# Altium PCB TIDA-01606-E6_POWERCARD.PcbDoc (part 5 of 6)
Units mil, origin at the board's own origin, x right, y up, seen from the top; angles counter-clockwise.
Board outline 13779.53 x 7874.02 mil, 4 copper layers (Top Layer, Gnd Layer, Pwr Layer, Bottom Layer), stack 94.4 mil thick; 550 components, 292 nets, 1594 pads, 572 vias.
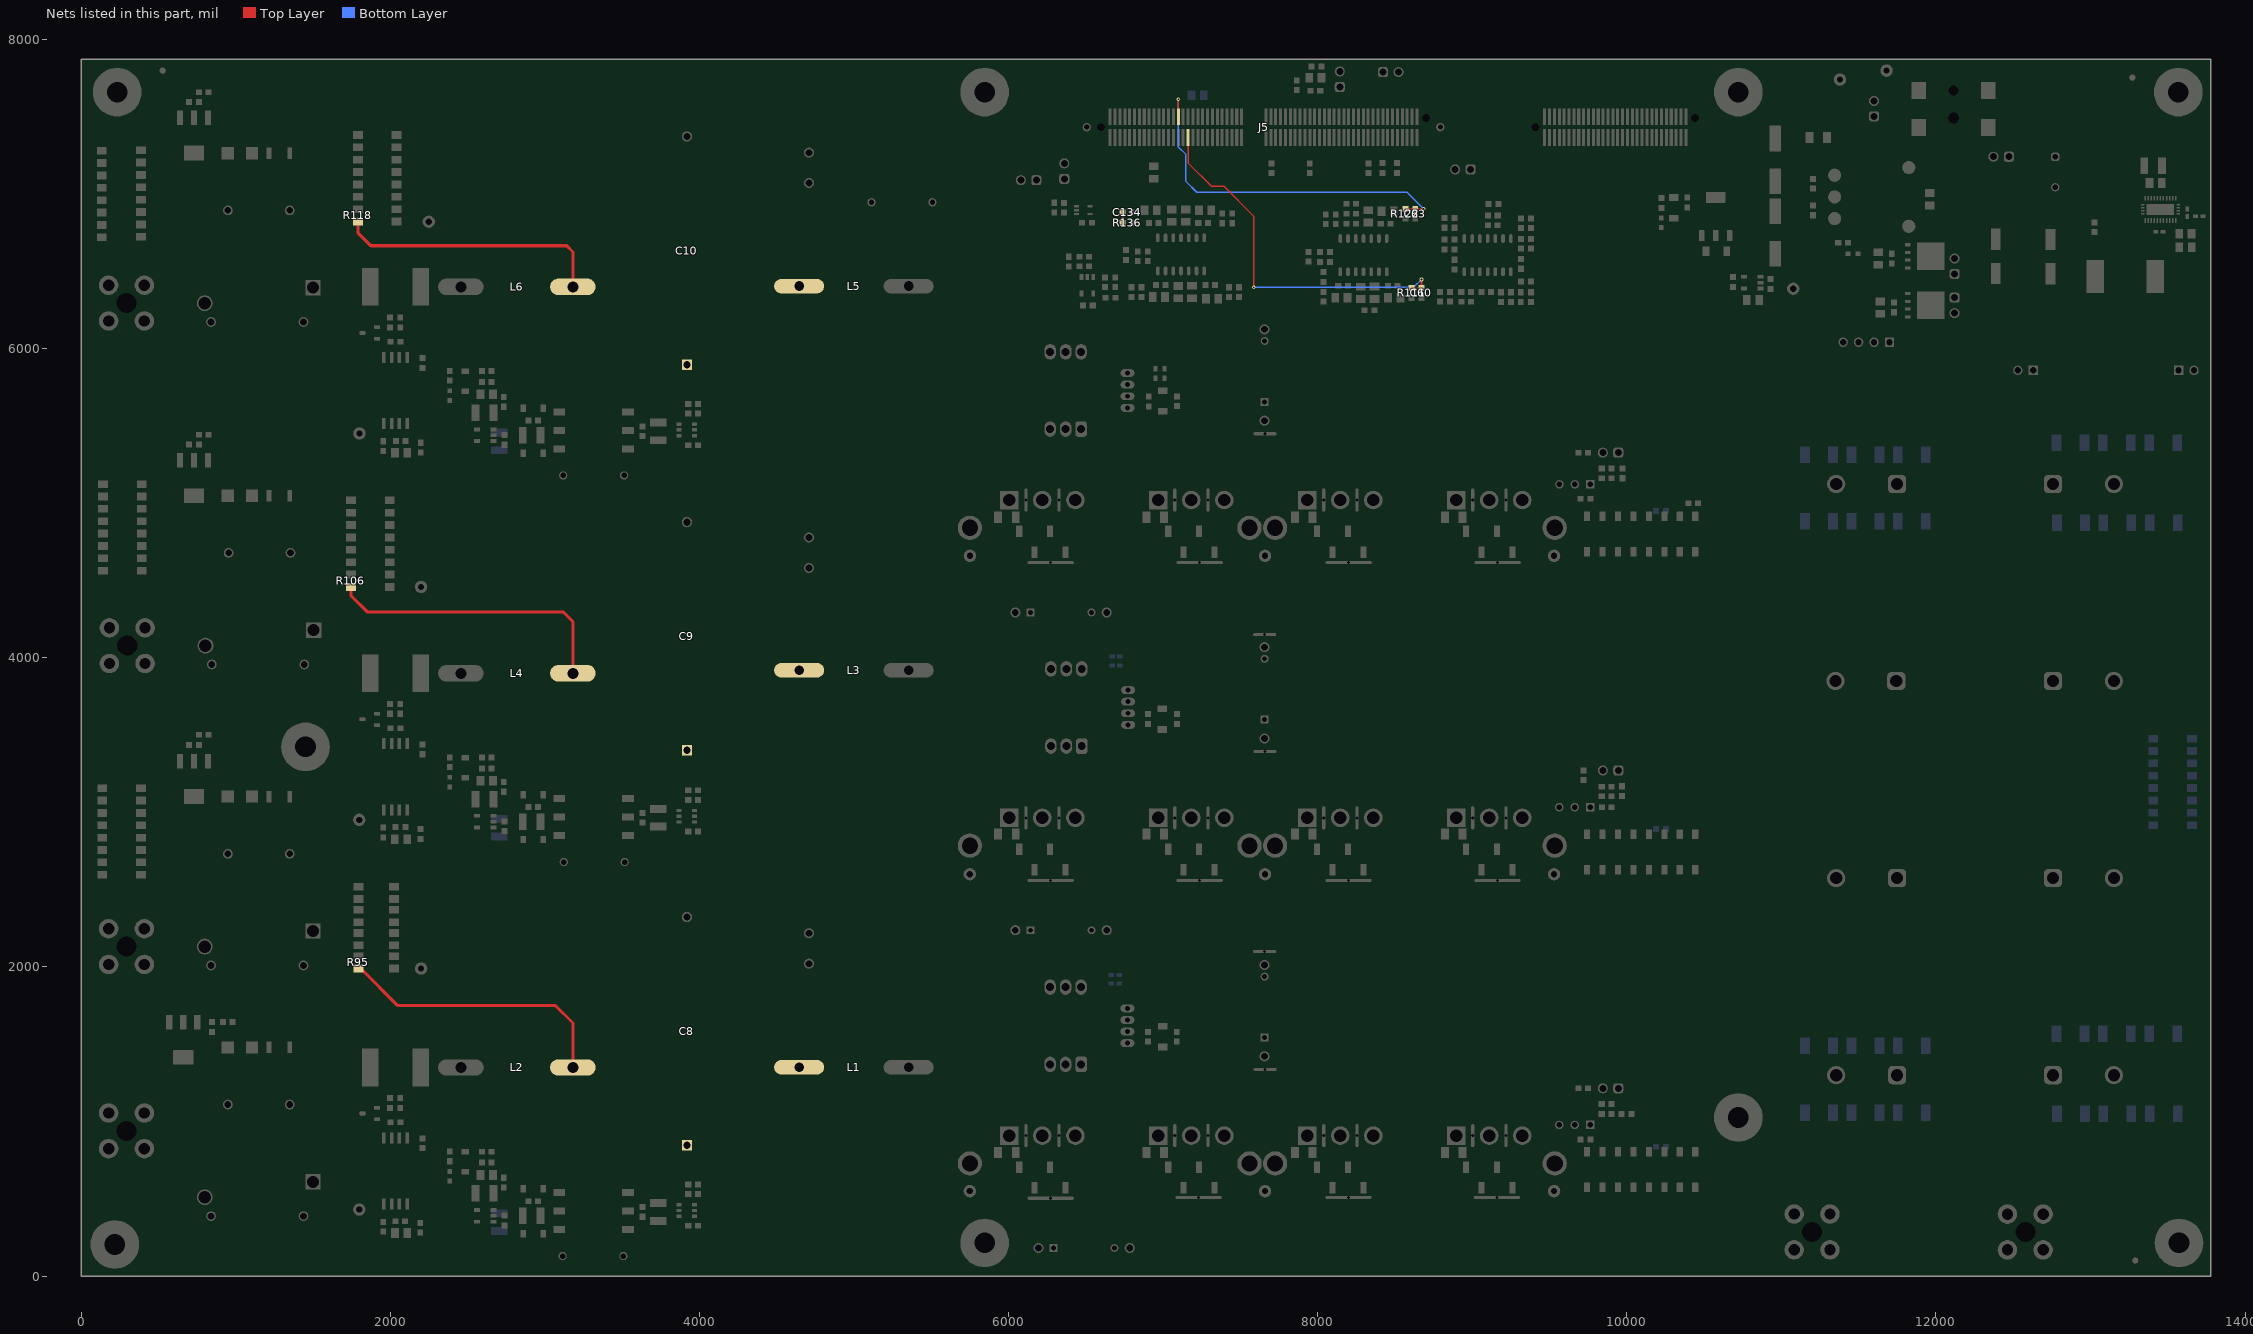
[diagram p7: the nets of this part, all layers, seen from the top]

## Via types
v1: diameter 32, hole 16, Top Layer to Bottom Layer, 336 vias
v2: diameter 24, hole 12, Top Layer to Bottom Layer, 140 vias
v3: diameter 50, hole 28, Top Layer to Bottom Layer, tented both sides, 65 vias
v4: diameter 52, hole 28, Top Layer to Bottom Layer, 14 vias
v5: diameter 19.68, hole 7.87, Top Layer to Bottom Layer, 10 vias
v6: diameter 50, hole 28, Top Layer to Bottom Layer, 7 vias

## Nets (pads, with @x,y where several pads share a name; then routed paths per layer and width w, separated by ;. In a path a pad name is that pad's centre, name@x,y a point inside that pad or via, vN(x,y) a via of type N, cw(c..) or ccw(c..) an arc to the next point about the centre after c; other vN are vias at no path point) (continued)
VINV_SEN_B: C60.2 J5.33 R111.2 | length 2417.9
  Top Layer w10: J5.33@7161.93,7366.21 7161.92,7202.07 7312,7052 7392,7052 7586,6858 7586,6398 v2(7587,6397) ; R111.2@8607.7,6392.5 C60.2@8671.7,6392.5 8672,6392.8 v2(8672,6448)
  Bottom Layer w10: v2(7587,6397) 8621,6397 v2(8672,6448)
VINV_SEN_C: C63.2 J5.30 R122.2 | length 2400.2
  Top Layer w10: J5.30@7098.93,7500.07 7098.93,7615.56 7099,7615.5 v2(7099,7614) ; R122.2@8567.7,6904.5 C63.2@8631.7,6904.5 8631,6905.2 v2(8685.8,6905.2)
  Bottom Layer w10: v2(7099,7614) 7099,7305 7148,7256 7148,7082 7218,7012 8579,7012 v2(8685.8,6905.2)
VMID_SEN_C: C134.2 R136.2 | length 69.9
  Top Layer w10: R136.2@6738.5,6813.43 C134.2@6738.5,6883.38
Vsen_A: C8.1 L1.1 L2.1 R95.1 | length 1820.9
  Top Layer w20: R95.1@1795,1990 1809.64,1990 2049.64,1750 3070,1750 3182.2,1637.8 L2.1@3182.2,1350
Vsen_B: C9.1 L3.1 L4.1 R106.1 | length 1895.9
  Top Layer w20: R106.1@1746.45,4459 1746.45,4401.59 1850.63,4297.4 3117.6,4297.4 3182.2,4232.8 L4.1@3182.2,3900
Vsen_C: C10.1 L5.1 L6.1 R118.1 | length 1741.6
  Top Layer w20: R118.1@1791.06,6823 1791.06,6750.03 1875.2,6665.89 3142.5,6665.89 3182.2,6626.19 L6.1@3182.2,6400
pads on no net: FID1.1 FID2.1 FID3.1 FID4.1 FID5.1 FID6.1 H1.0 H2.0 H3.0 H4.0 H5.0 H6.0 H7.0 H8.0 H9.0 H10.0 H11.0 H12.0 H13.0 H14.0 H15.0 H16.0 H17.0 H18.0 H19.1 H19.2 H20.1 H20.2 H21.1 H21.2 H22.1 H22.2 H23.1 H23.2 H24.1 H24.2 J1. J2. J3. J4. J5.1 J5.2 J5.3 J5.4 J5.5 J5.6 J5.8 J5.23 J5.24 J5.26 J5.27 J5.36 J5.39 J5.40 J5.41 J5.43 J5.44 J5.45 J5.66 J5.67 J5.68 J5.69 J5.70 J5.71 J5.72 J5.73 J5.74 J5.77 J5.78 J5.80 J5.82 J5.91 J5.93 J5.94 J5.96 J5.100 J5.102 J5.104 J5.106 J5.113 J5.114 J5.115 J5.116 J5.117 J5.118 J5.119 J5.120 J5.181 J5.182 J5.185 J5.186 J7.3 J7.4 J9.3 J12.3 J13.61 J13.62 J13.121 J13.122 J13.123 J13.124 J13.125 J13.126 J13.127 J13.128 J13.129 J13.130 J13.131 J13.132 J13.133 J13.134 J13.135 J13.136 J13.137 J13.138 J13.139 J13.140 J13.141 J13.142 J13.143 J13.144 J13.145 J13.146 J13.147 J13.148 J13.149 J13.150 J13.151 J13.152 J13.153 J13.154 J13.155 J13.156 J13.157 J13.159 J13.160 J13.161 J13.162 J13.163 J13.164 J13.165 J13.166 J13.167 J13.168 J13.169 J13.170 J13.171 J13.172 J13.173 J13.174 J13.175 J13.176 J13.177 J13.178 J14.3 J14.4 J15.3 J16.3 J17.3 J18.3 J18.4 J19.3 J19.4 J20.3 J21.3 J21.4 J22.3 J22.4 J23.9 J24.9 J25.9 J31. J32. J33.MH1 J33.MH2 LBL1.0 Q13.9@11912.28,6223.91 Q13.9@11912.28,6281 Q13.9@11912.28,6338.09 Q13.9@11948.9,6281 Q13.9@11982.36,6223.91 Q13.9@11982.36,6281 Q13.9@11982.36,6338.09 Q14.9@11913.04,6540.66 Q14.9@11913.04,6597.75 Q14.9@11913.04,6654.83 Q14.9@11949.65,6597.75 Q14.9@11983.12,6540.66 Q14.9@11983.12,6597.75 Q14.9@11983.12,6654.83 R177.1 U10.4 U10.5 U11.10 U11.11 U11.31@13385.31,6881.46 U11.31@13385.31,6920.83 U11.31@13430.19,6881.46 U11.31@13430.19,6920.83 U11.31@13475.07,6881.46 U11.31@13475.07,6920.83 U11.31@13519.95,6881.46 U11.31@13519.95,6920.83 U12.5 U21.4 U21.5 U23.4 U23.5

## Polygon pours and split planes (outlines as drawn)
DC- on Top Layer "GN" (solid, remove dead copper, pour order 826): 55 vertices, not listed, extent 6387,37 11414,5204
Vsen_B on Top Layer "GN" (solid, remove dead copper, pour order 820): 3010,3380 3010,4000 3030,4020 4790,4020 4830,3980 4830,3600 4790,3560 4180,3560 3980,3360 3050,3360 3030,3360
Q4A on Top Layer "TOP_LAYER_Q4A_P818" (solid, remove dead copper, pour order 818): 8981.34,667.87 8981.34,937.87 8961.34,957.87 8861.34,957.87 8861.34,687.87 8881.34,667.87
Q3A on Top Layer "TOP_LAYER_Q3A_P816" (solid, remove dead copper, pour order 816): 8017.56,667.87 8017.56,937.87 7997.56,957.87 7897.56,957.87 7897.56,687.87 7917.56,667.87
Q1A on Top Layer "TOP_LAYER_Q1A_P814" (solid, remove dead copper, pour order 814): 7053.78,667.87 7053.78,937.87 7033.78,957.87 6933.78,957.87 6933.78,687.87 6953.78,667.87
Q2A on Top Layer "TOP_LAYER_Q2A_P812" (solid, remove dead copper, pour order 812): 6090,667.87 6090,937.87 6070,957.87 5970,957.87 5970,687.87 5990,667.87
Q4B on Top Layer "TOP_LAYER_Q4B_P810" (solid, remove dead copper, pour order 810): 8981.34,2723.94 8981.34,2993.94 8961.34,3013.94 8861.34,3013.94 8861.34,2743.94 8881.34,2723.94
Q3B on Top Layer "TOP_LAYER_Q3B_P808" (solid, remove dead copper, pour order 808): 8017.56,2723.94 8017.56,2993.94 7997.56,3013.94 7897.56,3013.94 7897.56,2743.94 7917.56,2723.94
Q1B on Top Layer "TOP_LAYER_Q1B_P806" (solid, remove dead copper, pour order 806): 7053.78,2723.94 7053.78,2993.94 7033.78,3013.94 6933.78,3013.94 6933.78,2743.94 6953.78,2723.94
Q2B on Top Layer "TOP_LAYER_Q2B_P804" (solid, remove dead copper, pour order 804): 6090,2723.94 6090,2993.94 6070,3013.94 5970,3013.94 5970,2743.94 5990,2723.94
Q4C on Top Layer "TOP_LAYER_Q4C_P802" (solid, remove dead copper, pour order 802): 8981.34,4780 8981.34,5050 8961.34,5070 8861.34,5070 8861.34,4800 8881.34,4780
Q3C on Top Layer "TOP_LAYER_Q3C_P800" (solid, remove dead copper, pour order 800): 8017.56,4780 8017.56,5050 7997.56,5070 7897.56,5070 7897.56,4800 7917.56,4780
Q1C on Top Layer "TOP_LAYER_Q1C_P798" (solid, remove dead copper, pour order 798): 7053.78,4780 7053.78,5050 7033.78,5070 6933.78,5070 6933.78,4800 6953.78,4780
Vsen_A on Top Layer "GN" (solid, remove dead copper, pour order 766): 3010,830 3010,1450 3030,1470 4780,1470 4830,1420 4830,1060 4780,1010 4180,1010 3980,810 3030,810
NetC8_2 on Top Layer "TOP_LAYER_NETC8_2_P758" (solid, remove dead copper, pour order 758): 3860,2370 3860,2310 3890,2280 4570,2280 4690,2160 4740,2160 4770,2190 4770,2280 4770,2370 4740,2400 3890,2400
NetC9_2 on Top Layer "TOP_LAYER_NETC9_2_P756" (solid, remove dead copper, pour order 756): 3860,4930 3860,4860 3885,4835 4570,4835 4690,4715 4745,4715 4770,4740 4770,4835 4770,4930 4745,4955 3885,4955
Vinv_B on Top Layer "M1 Board Outline-No Net" (solid, remove dead copper, pour order 690): 1915,3760 1590,3760 1410,3940 1410,4220 1428,4238 1614,4238 1802,4050 1915,4050 1925,4040 1925,3770
3.3V on Top Layer "GN" (solid, remove dead copper, pour order 686): 2267,5364 2174,5364 2161,5377 2161,5459 2178,5476 2257,5476 2269,5464 2269,5366 2267,5364
3.3V on Top Layer "GN" (solid, remove dead copper, pour order 684): 2267,314 2174,314 2161,327 2161,409 2178,426 2257,426 2269,414 2269,316 2267,314
3.3V on Top Layer "GN" (solid, remove dead copper, pour order 678): 2267,2864 2174,2864 2161,2877 2161,2959 2178,2976 2257,2976 2269,2964 2269,2866 2267,2864
QC_N on Top Layer "GN" (solid, remove dead copper, pour order 508): 25 vertices, not listed, extent 8316,4963 9421,5382
IIND_C on Top Layer "GN" (solid, remove dead copper, pour order 502): 39 vertices, not listed, extent 6169,4969 8194,5530
IGRID_A on Top Layer "TOP_LAYER_IGRID_A_P054" (solid, remove dead copper, pour order 54): 2611,1465 2611,1247 2574,1210 2153.9,1210 2143.9,1220 2143.9,1490 2153.9,1500 2576,1500
IGRID_B on Top Layer "TOP_LAYER_IGRID_B_P048" (solid, remove dead copper, pour order 48): 2610,4020 2610,3789 2581,3760 2153.9,3760 2143.9,3770 2143.9,4040 2153.9,4050 2580,4050
IGRID_C on Top Layer "TOP_LAYER_IGRID_C_P038" (solid, remove dead copper, pour order 38): 2610,6527 2610,6282 2588,6260 2153.9,6260 2143.9,6270 2143.9,6540 2153.9,6550 2587,6550
Vinv_C on Top Layer "TOP_LAYER_VINV_C_P036" (solid, remove dead copper, pour order 36): 1620,6260 1489.56,6129.56 1427.69,6129.56 1408.19,6149.06 1408.19,6534.78 1423.41,6550 1465,6550 1915,6550 1925,6540 1925,6270 1915,6260
NEU on Top Layer "TOP_LAYER_NEU_P010" (solid, remove dead copper, pour order 10): 90,1108 142,1160 420,1160 550,1030 880,700 880,362.72 847.28,330 515,330 90,755
PH_C on Top Layer "TOP_LAYER_PH_C_P006" (solid, remove dead copper, pour order 6): 809,6552 879,6482 879,6109 825,6055 95,6055 70,6080 70,6513 109,6552
NetC10_2 on Top Layer "TOP_LAYER_NETC10_2_P084" (solid, remove dead copper, pour order 84): 3860,7430 3860,7350 3880,7330 4570,7330 4690,7210 4740,7210 4770,7240 4770,7330 4770,7420 4740,7450 3880,7450
PH_B on Top Layer "TOP_LAYER_PH_B_P086" (solid, remove dead copper, pour order 86): 814,4336 880,4270 880,3889 830,3839 100,3839 75,3864 75,4297 114,4336
PH_A on Top Layer "TOP_LAYER_PH_A_P088" (solid, remove dead copper, pour order 88): 809,2389 879,2319 879,1946 825,1892 95,1892 70,1917 70,2350 109,2389
Vinv_A on Top Layer "M1 Board Outline-No Net" (solid, remove dead copper, pour order 116): 1410,2268.66 1410,1934 1729,1615 1729,1248 1752,1225 1843,1225 1923,1225 1928,1230 1928,1750 1658,2020 1658,2278 1644,2292 1433.34,2292
NetC31_1 on Top Layer "M1 Board Outline-No Net" (solid, remove dead copper, pour order 212): 7122,5651 7131,5642 7131,5581 7121,5571 6756,5571 6746,5581 6741,5586 6741,5631 6741,5639 6753,5651
5V on Top Layer "M1 Board Outline-No Net" (solid, remove dead copper, pour order 214): 7056,5683 7056,5764 7064,5772 7170,5772 7178,5764 7178,5678 7166,5666 7066,5666 7056,5676
GND on Top Layer "M1 Board Outline-No Net" (solid, remove dead copper, pour order 216): 6962,5775 6908,5775 6896,5763 6842,5709 6807,5709 6751,5709 6744,5702 6744,5681 6748,5677 7009,5677 7033,5701 7033,5765 7023,5775
GND on Top Layer "M1 Board Outline-No Net" (solid, remove dead copper, pour order 218): 6962,3718.94 6908,3718.94 6896,3706.94 6842,3652.94 6807,3652.94 6751,3652.94 6744,3645.94 6744,3624.94 6748,3620.94 7009,3620.94 7033,3644.94 7033,3708.94 7023,3718.94
5V on Top Layer "M1 Board Outline-No Net" (solid, remove dead copper, pour order 220): 7056,3626.94 7056,3707.94 7064,3715.94 7170,3715.94 7178,3707.94 7178,3621.94 7166,3609.94 7066,3609.94 7056,3619.94
NetC24_1 on Top Layer "M1 Board Outline-No Net" (solid, remove dead copper, pour order 222): 7122,3594.94 7131,3585.94 7131,3524.94 7121,3514.94 6756,3514.94 6746,3524.94 6741,3529.94 6741,3574.94 6741,3582.94 6753,3594.94
GND on Top Layer "M1 Board Outline-No Net" (solid, remove dead copper, pour order 224): 6962,1662.87 6908,1662.87 6896,1650.87 6842,1596.87 6807,1596.87 6751,1596.87 6744,1589.87 6744,1568.87 6748,1564.87 7009,1564.87 7033,1588.87 7033,1652.87 7023,1662.87
5V on Top Layer "M1 Board Outline-No Net" (solid, remove dead copper, pour order 226): 7056,1570.87 7056,1651.87 7064,1659.87 7170,1659.87 7178,1651.87 7178,1565.87 7166,1553.87 7066,1553.87 7056,1563.87
NetC22_1 on Top Layer "M1 Board Outline-No Net" (solid, remove dead copper, pour order 228): 7122,1538.87 7131,1529.87 7131,1468.87 7121,1458.87 6756,1458.87 6746,1468.87 6741,1473.87 6741,1518.87 6741,1526.87 6753,1538.87
DC+ on Top Layer "M1 Board Outline-No Net" (solid, remove dead copper, pour order 242): 12336.85,73.15 12374,36 12793,36 12816.85,59.85 12816.85,5131 12793.85,5154 12368.85,5154 12336.85,5122
PGND on Top Layer "M1 Board Outline-No Net" (solid, remove dead copper, pour order 246): 11690,1342 11690,5182 11712,5204 12096,5204 12117,5183 12117,1253 12093,1229 11713,1229 11690,1252
PGND on Top Layer "M1 Board Outline-No Net" (solid, remove dead copper, pour order 248): 13092.85,1342 13092.85,5182 13114.85,5204 13498.85,5204 13519.85,5183 13519.85,1253 13495.85,1229 13115.85,1229 13092.85,1252
NetC20_1 on Top Layer "M1 Board Outline-No Net" (solid, remove dead copper, pour order 250): 19 vertices, not listed, extent 2081,243 2232.55,503
GND on Top Layer "M1 Board Outline-No Net" (solid, remove dead copper, pour order 252): 2002,357 2002,265 1993,256 1958,256 1953,251 1953,182 1958,177 2050,177 2055,182 2055,374 2052,377 2007,377 2002,372
5V_1 on Top Layer "M1 Board Outline-No Net" (solid, remove dead copper, pour order 254): 17 vertices, not listed, extent 2094,783 2614,934
Vinv_A on Top Layer "M1 Board Outline-No Net" (solid, remove dead copper, pour order 256): 20 vertices, not listed, extent 2936,328 3133,512.27
+6V_VDC_1 on Top Layer "M1 Board Outline-No Net" (solid, remove dead copper, pour order 258): 22 vertices, not listed, extent 2646,230 2896,610
NetC105_2 on Top Layer "M1 Board Outline-No Net" (solid, remove dead copper, pour order 262): 2677,415 2645,415 2640,420 2640,590 2643,593 2750,593 2754,589 2754,492
NetC101_2 on Top Layer "M1 Board Outline-No Net" (solid, remove dead copper, pour order 264): 2636,796 2636,622 2641,617 2754,617 2756,619 2756,647 2756,656 2752,660 2711,660 2705,666 2705,822 2700,827 2640,827 2636,823
Vinv_A on Top Layer "M1 Board Outline-No Net" (solid, remove dead copper, pour order 266): 17 vertices, not listed, extent 2358,476 2610,755
NetC61_1 on Top Layer "M1 Board Outline-No Net" (solid, remove dead copper, pour order 452): 19 vertices, not listed, extent 10895,7073 11392,7467
5V on Top Layer "M1 Board Outline-No Net" (solid, remove dead copper, pour order 454): 29 vertices, not listed, extent 10615.13,6522 11390,6886
GND on Top Layer "GN" (solid, remove dead copper, pour order 456): 21 vertices, not listed, extent 10855,6810 11393,7166
3.3V on Top Layer "GN" (solid, remove dead copper, pour order 460): 20 vertices, not listed, extent 10192,6695 10696,7127
GND on Top Layer "GN" (solid, remove dead copper, pour order 464): 11838.25,6252.25 11838.25,6380.36 11835.25,6383.36 11699.36,6383.36 11691.25,6375.25 11691.25,6285.25 11696.25,6280.25 11765.25,6280.25 11799.25,6246.25 11834.25,6246.25 11838.25,6250.25
GND on Top Layer "GN" (solid, remove dead copper, pour order 466): 11824,6570 11824,6698.12 11821,6701.12 11685.11,6701.12 11677,6693 11677,6603 11682,6598 11751,6598 11785,6564 11820,6564 11824,6568
3.3V_U9 on Top Layer "GN" (solid, remove dead copper, pour order 468): 18 vertices, not listed, extent 9034.7,6681 9132,6982
+12V on Top Layer "GN" (solid, remove dead copper, pour order 474): 1313,6910 1313,7307 1313,7312 1319,7318 1320,7319 1339,7319 1367,7319 1378,7319 1387,7310 1387,6870 1378,6861 1334,6861 1320,6861 1313,6868 1313,6869
+12V on Top Layer "GN" (solid, remove dead copper, pour order 476): 1318,4694 1318,5091 1318,5096 1324,5102 1325,5103 1344,5103 1372,5103 1383,5103 1392,5094 1392,4654 1383,4645 1339,4645 1325,4645 1318,4652 1318,4653
+12V on Top Layer "GN" (solid, remove dead copper, pour order 482): 1313,2747 1313,3144 1313,3149 1319,3155 1320,3156 1339,3156 1367,3156 1378,3156 1387,3147 1387,2707 1378,2698 1334,2698 1320,2698 1313,2705 1313,2706
+12V on Top Layer "GN" (solid, remove dead copper, pour order 486): 1313,1125 1313,1522 1313,1527 1319,1533 1320,1534 1339,1534 1367,1534 1378,1534 1387,1525 1387,1085 1378,1076 1334,1076 1320,1076 1313,1083 1313,1084
3.3V_U19 on Top Layer "GN" (solid, remove dead copper, pour order 488): 7969,6588 8297,6588 8311,6574 8311,6472 8305,6466 8290,6466 8282,6474 8282,6532 8273,6541 7912,6541 7905,6548 7905,6583 7910,6588
3.3V_U18 on Top Layer "GN" (solid, remove dead copper, pour order 490): 6788.41,6593 7116.41,6593 7130.41,6579 7130.41,6477 7124.41,6471 7109.41,6471 7101.41,6479 7101.41,6537 7092.41,6546 6731.41,6546 6724.41,6553 6724.41,6588 6729.41,6593
QB_N on Top Layer "GN" (solid, remove dead copper, pour order 534): 25 vertices, not listed, extent 8316,2906.94 9421,3325.94
QA_N on Top Layer "GN" (solid, remove dead copper, pour order 550): 25 vertices, not listed, extent 8316,850.87 9421,1269.87
Vsen_C on Top Layer "GN" (solid, remove dead copper, pour order 570): 3010,5880 3010,6500 3030,6520 4790,6520 4830,6480 4830,6110 4780,6060 4180,6060 3980,5860 3030,5860
IIND_C_RTN on Top Layer "GN" (solid, remove dead copper, pour order 586): 5170,6100 5170,6480 5210,6520 6040,6520 6480,6080 6530,6030 6530,5940 6490,5900 6020,5900 5860,6060 5210,6060
IIND_B_RTN on Top Layer "GN" (solid, remove dead copper, pour order 592): 5200,4060 6490,4060 6520,4030 6520,3840 6490,3810 5780,3810 5670,3690 5200,3690 5170,3720 5170,4030
IIND_A_RTN on Top Layer "GN" (solid, remove dead copper, pour order 598): 6500,2000 5720,2000 5190,1470 5190,1290 5230,1250 5770,1250 6240,1720 6490,1720 6540,1770 6540,1960
Vinv_B on Top Layer "M1 Board Outline-No Net" (solid, remove dead copper, pour order 602): 17 vertices, not listed, extent 2358,3026 2610,3305
NetC102_2 on Top Layer "M1 Board Outline-No Net" (solid, remove dead copper, pour order 604): 2636,3346 2636,3172 2641,3167 2754,3167 2756,3169 2756,3197 2756,3206 2752,3210 2711,3210 2705,3216 2705,3372 2700,3377 2640,3377 2636,3373
NetC106_2 on Top Layer "M1 Board Outline-No Net" (solid, remove dead copper, pour order 606): 2677,2965 2645,2965 2640,2970 2640,3140 2643,3143 2750,3143 2754,3139 2754,3042
+6V_VDC_2 on Top Layer "M1 Board Outline-No Net" (solid, remove dead copper, pour order 608): 22 vertices, not listed, extent 2646,2780 2896,3160
Vinv_B on Top Layer "M1 Board Outline-No Net" (solid, remove dead copper, pour order 610): 20 vertices, not listed, extent 2936,2878 3133,3062.27
5V_2 on Top Layer "M1 Board Outline-No Net" (solid, remove dead copper, pour order 612): 17 vertices, not listed, extent 2094,3333 2614,3484
GND on Top Layer "M1 Board Outline-No Net" (solid, remove dead copper, pour order 614): 2002,2907 2002,2815 1993,2806 1958,2806 1953,2801 1953,2732 1958,2727 2050,2727 2055,2732 2055,2924 2052,2927 2007,2927 2002,2922
NetC29_2 on Top Layer "M1 Board Outline-No Net" (solid, remove dead copper, pour order 616): 19 vertices, not listed, extent 2081,2793 2232.55,3053
Vinv_C on Top Layer "M1 Board Outline-No Net" (solid, remove dead copper, pour order 620): 17 vertices, not listed, extent 2358,5526 2610,5805
NetC114_2 on Top Layer "M1 Board Outline-No Net" (solid, remove dead copper, pour order 622): 2636,5846 2636,5672 2641,5667 2754,5667 2756,5669 2756,5697 2756,5706 2752,5710 2711,5710 2705,5716 2705,5872 2700,5877 2640,5877 2636,5873
NetC116_2 on Top Layer "M1 Board Outline-No Net" (solid, remove dead copper, pour order 624): 2677,5465 2645,5465 2640,5470 2640,5640 2643,5643 2750,5643 2754,5639 2754,5542
+6V_VDC_3 on Top Layer "M1 Board Outline-No Net" (solid, remove dead copper, pour order 626): 22 vertices, not listed, extent 2646,5280 2896,5660
Vinv_C on Top Layer "M1 Board Outline-No Net" (solid, remove dead copper, pour order 628): 20 vertices, not listed, extent 2936,5378 3133,5562.27
5V_3 on Top Layer "M1 Board Outline-No Net" (solid, remove dead copper, pour order 630): 17 vertices, not listed, extent 2094,5833 2614,5984
GND on Top Layer "M1 Board Outline-No Net" (solid, remove dead copper, pour order 632): 2002,5407 2002,5315 1993,5306 1958,5306 1953,5301 1953,5232 1958,5227 2050,5227 2055,5232 2055,5424 2052,5427 2007,5427 2002,5422
NetC14_2 on Top Layer "M1 Board Outline-No Net" (solid, remove dead copper, pour order 634): 19 vertices, not listed, extent 2081,5290 2232.55,5550
3.3V on Top Layer "GN" (solid, remove dead copper, pour order 694): 20 vertices, not listed, extent 6420,6785 6609,6954
24V on Top Layer "GN" (solid, remove dead copper, pour order 706): 12410,7473 12410,7208 12394,7192 12252,7192 12231,7213 12231,7707 12185,7753 11641,7753 11633,7761 11633,7831 11651.21,7849.21 12343.79,7849.21 12410,7783 12410,7719 12410,7621
IIND_B on Top Layer "GN" (solid, remove dead copper, pour order 708): 39 vertices, not listed, extent 6169,2912.94 8194,3473.94
IIND_A on Top Layer "GN" (solid, remove dead copper, pour order 710): 39 vertices, not listed, extent 6169,856.87 8194,1417.87
GND on Top Layer "GN" (solid, remove dead copper, pour order 462): 17 vertices, not listed, extent 10196.99,6535 10539,6928
+24V on Top Layer "Top Layer-No Net" (solid, pour order 726): 18 vertices, not listed, extent 12436,6958 13520,7456
GND on Top Layer "Top Layer-No Net" (solid, pour order 728): 38 vertices, not listed, extent 12223,6644 13653,7253
+12V on Top Layer "Top Layer-No Net" (solid, pour order 730): 21 vertices, not listed, extent 12075,6219.97 13091,6776
NetC19_1 on Top Layer "Top Layer-No Net" (solid, pour order 732): 13440,6825 13440,6617 13481,6576 13481,6330 13470,6319 13276,6319 13258,6337 13258,6829 13273,6844 13275,6846 13419,6846 13435,6846 13439,6842 13440,6841 13440,6824
Q2C on Top Layer "TOP_LAYER_Q2C_P774" (solid, remove dead copper, pour order 774): 6090,4780 6090,5050 6070,5070 5970,5070 5970,4800 5990,4780
NEU on Bottom Layer "BOTTOM_LAYER_NEU_P840" (solid, remove dead copper, pour order 840): 90,1108 142,1160 420,1160 550,1030 880,700 880,362.72 847.28,330 515,330 90,755
Vinv_C on Bottom Layer "BOTTOM_LAYER_VINV_C_P838" (solid, remove dead copper, pour order 838): 1620,6260 1489.56,6129.56 1427.69,6129.56 1408.19,6149.06 1408.19,6534.78 1423.41,6550 1465,6550 1915,6550 1925,6540 1925,6270 1915,6260
PH_A on Bottom Layer "BOTTOM_LAYER_PH_A_P836" (solid, remove dead copper, pour order 836): 809,2389 879,2319 879,1946 825,1892 95,1892 70,1917 70,2350 109,2389
PH_B on Bottom Layer "BOTTOM_LAYER_PH_B_P834" (solid, remove dead copper, pour order 834): 814,4336 880,4270 880,3889 830,3839 100,3839 75,3864 75,4297 114,4336
PH_C on Bottom Layer "BOTTOM_LAYER_PH_C_P832" (solid, remove dead copper, pour order 832): 809,6552 879,6482 879,6109 825,6055 95,6055 70,6080 70,6513 109,6552
Vinv_B on Bottom Layer "M1 Board Outline-No Net" (solid, remove dead copper, pour order 830): 1915,3760 1590,3760 1410,3940 1410,4220 1428,4238 1614,4238 1802,4050 1915,4050 1925,4040 1925,3770
DC+ on Bottom Layer "GN" (solid, remove dead copper, pour order 828): 63 vertices, not listed, extent 7067,36 12817,5902
Vsen_A on Bottom Layer "GN" (solid, remove dead copper, pour order 768): 3010,830 3010,1450 3030,1470 4780,1470 4830,1420 4830,1060 4780,1010 4180,1010 3980,810 3050,810 3030,810
Vsen_B on Bottom Layer "GN" (solid, remove dead copper, pour order 764): 3010,3380 3010,4000 3030,4020 4790,4020 4830,3980 4830,3600 4790,3560 4180,3560 3980,3360 3050,3360 3030,3360
NetC8_2 on Bottom Layer "BOTTOM_LAYER_NETC8_2_P760" (solid, remove dead copper, pour order 760): 3860,2370 3860,2310 3890,2280 4570,2280 4690,2160 4740,2160 4770,2190 4770,2280 4770,2370 4740,2400 3890,2400
NetC9_2 on Bottom Layer "BOTTOM_LAYER_NETC9_2_P754" (solid, remove dead copper, pour order 754): 3860,4930 3860,4860 3885,4835 4570,4835 4690,4715 4745,4715 4770,4740 4770,4835 4770,4930 4745,4955 3885,4955
NetC10_2 on Bottom Layer "BOTTOM_LAYER_NETC10_2_P752" (solid, remove dead copper, pour order 752): 3860,7430 3860,7350 3880,7330 4570,7330 4690,7210 4740,7210 4770,7240 4770,7330 4770,7420 4740,7450 3880,7450
IIND_A_RTN on Bottom Layer "GN" (solid, remove dead copper, pour order 750): 6500,2000 5720,2000 5190,1470 5190,1290 5230,1250 5770,1250 6240,1720 6490,1720 6540,1770 6540,1960
IIND_B_RTN on Bottom Layer "GN" (solid, remove dead copper, pour order 748): 5200,4060 6490,4060 6520,4030 6520,3840 6490,3810 5780,3810 5670,3690 5200,3690 5170,3720 5170,4030
3.3V on Bottom Layer "GN" (solid, remove dead copper, pour order 688): 2267,5364 2174,5364 2161,5377 2161,5459 2178,5476 2257,5476 2269,5464 2269,5366 2267,5364
3.3V on Bottom Layer "GN" (solid, remove dead copper, pour order 682): 2267,314 2174,314 2161,327 2161,409 2178,426 2257,426 2269,414 2269,316 2267,314
3.3V on Bottom Layer "GN" (solid, remove dead copper, pour order 680): 2267,2864 2174,2864 2161,2877 2161,2959 2178,2976 2257,2976 2269,2964 2269,2866 2267,2864
Vinv_A on Bottom Layer "M1 Board Outline-No Net" (solid, remove dead copper, pour order 358): 1410,2268.66 1410,1934 1729,1615 1729,1248 1752,1225 1843,1225 1923,1225 1928,1230 1928,1750 1658,2020 1658,2278 1644,2292 1433.34,2292
IGRID_C on Bottom Layer "BOTTOM_LAYER_IGRID_C_P346" (solid, remove dead copper, pour order 346): 2610,6527 2610,6282 2588,6260 2153.9,6260 2143.9,6270 2143.9,6540 2153.9,6550 2587,6550
IGRID_B on Bottom Layer "BOTTOM_LAYER_IGRID_B_P344" (solid, remove dead copper, pour order 344): 2609,4021.62 2609,3788 2581,3760 2153.9,3760 2143.9,3770 2143.9,4040 2153.9,4050 2580.62,4050
IGRID_A on Bottom Layer "BOTTOM_LAYER_IGRID_A_P342" (solid, remove dead copper, pour order 342): 2611,1465 2611,1247 2574,1210 2153.9,1210 2143.9,1220 2143.9,1490 2153.9,1500 2576,1500
+6V_VDC_1 on Bottom Layer "M1 Board Outline-No Net" (solid, remove dead copper, pour order 260): 2793,373 2658,373 2649,382 2649,470 2657,478 2820,478 2826,472 2829,469 2829,441 2829,386 2816,373
Vsen_C on Bottom Layer "GN" (solid, remove dead copper, pour order 574): 3010,5880 3010,6500 3030,6520 4790,6520 4830,6480 4830,6110 4780,6060 4180,6060 3980,5860 3030,5860
IIND_C_RTN on Bottom Layer "GN" (solid, remove dead copper, pour order 588): 5170,6100 5170,6480 5210,6520 6040,6520 6480,6080 6530,6030 6530,5940 6490,5900 6020,5900 5860,6060 5210,6060
+6V_VDC_2 on Bottom Layer "M1 Board Outline-No Net" (solid, remove dead copper, pour order 618): 2793,2923 2658,2923 2649,2932 2649,3020 2657,3028 2820,3028 2826,3022 2829,3019 2829,2991 2829,2936 2816,2923
+6V_VDC_3 on Bottom Layer "M1 Board Outline-No Net" (solid, remove dead copper, pour order 636): 2793,5423 2658,5423 2649,5432 2649,5520 2657,5528 2820,5528 2826,5522 2829,5519 2829,5491 2829,5436 2816,5423
+12V on Bottom Layer "Top Layer-No Net" (solid, pour order 734): 12702,6538 12089,6538 12075,6524 12075,6307.74 12094.24,6288.5 12273.5,6288.5 12280,6282 12342.03,6219.97 12699.97,6219.97 12739,6259 12739,6501
3.3V on Pwr Layer "GN" (solid, remove dead copper, pour order 692): 5771,7403 6068,7403 6408,7743 6481,7816 11173,7816 11231,7758 11231,6308 11196,6273 11147,6224 10954,6031 8106,6031 7881,6256 7873,6264 7575,6264 5771,6264
5V on Pwr Layer "GN" (solid, remove dead copper, pour order 672): 9997,5966 10580,6549 10733,6702 10881,6702 10909,6674 10909,6670 10909,6244 10695,6030 10331,5666 7166,5666 7045,5666 7018,5693 7018,5938 7046,5966
5V on Pwr Layer "M1 Board Outline-No Net" (solid, remove dead copper, pour order 658): 7055.97,1571 7055.97,1652 7063.97,1660 7169.97,1660 7177.97,1652 7177.97,1566 7165.97,1554 7065.97,1554 7055.97,1564
5V on Pwr Layer "M1 Board Outline-No Net" (solid, remove dead copper, pour order 656): 7056,3626.94 7056,3707.94 7064,3715.94 7170,3715.94 7178,3707.94 7178,3621.94 7166,3609.94 7066,3609.94 7056,3619.94
5V on Pwr Layer "M1 Board Outline-No Net" (solid, remove dead copper, pour order 654): 7056,5683 7056,5764 7064,5772 7170,5772 7178,5764 7178,5678 7166,5666 7066,5666 7056,5676
5V_3 on Pwr Layer "GN" (solid, remove dead copper, pour order 650): 27 vertices, not listed, extent 1787,5266 3141,6230
5V_2 on Pwr Layer "GN" (solid, remove dead copper, pour order 648): 27 vertices, not listed, extent 1787,2766 3141,3730
5V_1 on Pwr Layer "GN" (solid, remove dead copper, pour order 646): 27 vertices, not listed, extent 1787,216 3141,1180
IIND_C on Pwr Layer "GN" (solid, remove dead copper, pour order 512): 39 vertices, not listed, extent 6169,4969 8194,5530
QC_N on Pwr Layer "GN" (solid, remove dead copper, pour order 510): 25 vertices, not listed, extent 8316,4963 9421,5382
QB_N on Pwr Layer "GN" (solid, remove dead copper, pour order 560): 25 vertices, not listed, extent 8316,2906.94 9421,3325.94
IIND_B on Pwr Layer "GN" (solid, remove dead copper, pour order 562): 39 vertices, not listed, extent 6169,2912.94 8194,3473.94
QA_N on Pwr Layer "GN" (solid, remove dead copper, pour order 564): 25 vertices, not listed, extent 8316,850.87 9421,1269.87
IIND_A on Pwr Layer "GN" (solid, remove dead copper, pour order 566): 39 vertices, not listed, extent 6169,856.87 8194,1417.87
+12V on Pwr Layer "Top Layer-No Net" (solid, pour order 736): 12702,6538 12089,6538 12075,6524 12075,6307.74 12092.74,6290 12272,6290 12280,6282 12342.03,6219.97 12699.97,6219.97 12739,6259 12739,6501
Vinv_A on Gnd Layer "GN" (solid, remove dead copper, pour order 644): 27 vertices, not listed, extent 1787,216 3141,1180
Vinv_B on Gnd Layer "GN" (solid, remove dead copper, pour order 642): 27 vertices, not listed, extent 1787,2766 3141,3730
Vinv_C on Gnd Layer "GN" (solid, remove dead copper, pour order 640): 27 vertices, not listed, extent 1787,5266 3141,6230
PGND on Gnd Layer "GND_LAYER_PGND_P714" (solid, remove dead copper, pour order 714): 25 vertices, not listed, extent 25.49,25 13754.04,7482
GND on Gnd Layer "GND_LAYER_GND_P716" (solid, remove dead copper, pour order 716): 20 vertices, not listed, extent 53,5809 13754.04,7848.53

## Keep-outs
Gnd Layer:
  circle w10: c10723.06,7660 r205
  circle w10: c13574.75,215 r205
  circle w10: c10723.05,1026 r205
  circle w10: c13569.76,7660 r205
  circle w10: c5847.58,7660 r205
  circle w10: c236.03,7660 r205
  circle w10: c5843.58,215 r205
  circle w10: c219.98,205 r205
  circle w10: c1800.67,5451.82 r85
  circle w10: c1800,2952 r85
  circle w10: c1800,430.55 r85
  circle w10: c1453.53,3424 r205
Pwr Layer:
  circle w10: c10723.59,7660 r205
Keep-Out Layer:
  text ".Layer_Name" at -13.55,-858.49 h60

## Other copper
Top Layer:
  text ".Layer_Name" at -13.55,-858.49 h60
Gnd Layer:
  pour cut-out: 3457.98,180.73 3457.98,80.73 3558.98,80.73 3558.98,180.73
  pour cut-out: 3064.28,180.73 3064.28,80.73 3165.28,80.73 3165.28,180.73
  pour cut-out: 3072.15,2729.64 3072.15,2629.64 3173.15,2629.64 3173.15,2729.64
  pour cut-out: 3465.85,2729.64 3465.85,2629.64 3566.85,2629.64 3566.85,2729.64
  pour cut-out: 3461.85,5230.73 3461.85,5130.73 3562.85,5130.73 3562.85,5230.73
  pour cut-out: 3068.15,5230.73 3068.15,5130.73 3169.15,5130.73 3169.15,5230.73
  pour cut-out: 1620,5920 1850,5690 1850,5200 1890,5160 3450,5160 3480,5190 3480,5820 3450,5850 3160,5850 3160,5250 3150,5240 2450,5240 2310,5376 2310,5645 2160,5800 2160,5900 1790,5900 1790,6240 2160,6240 2260,6140 2610,6140 2770,5980 2770,5730 3130,5730 3160,5700 3160,5850 2640,6370 2640,6530 2590,6580 1660,6580 1620,6540
  pour cut-out: 12440,5770 12720,5770 12720,5950 12440,5950
  pour cut-out: 690,6395 690,6109 910,6109 910,6395
  pour cut-out: 6597,92.55 6882.93,92.55 6882.93,272.55 6597,272.55
  pour cut-out: 6443.87,2150.48 6729.8,2150.48 6729.8,2330.48 6443.87,2330.48
  pour cut-out: 6443.87,4206.54 6729.8,4206.54 6729.8,4386.54 6443.87,4386.54
  pour cut-out: 11240.58,5249.42 11240.58,5010.58 11479.42,5010.58 11479.42,5249.42
  pour cut-out: 12638.43,5243.9 12638.43,5005.06 12877.27,5005.06 12877.27,5243.9
  pour cut-out: 12638.43,3969.42 12638.43,3730.58 12877.27,3730.58 12877.27,3969.42
  pour cut-out: 11230.58,3969.42 11230.58,3730.58 11469.42,3730.58 11469.42,3969.42
  pour cut-out: 12638.43,2694.42 12638.43,2455.58 12877.27,2455.58 12877.27,2694.42
  pour cut-out: 11235.58,2694.42 11235.58,2455.58 11474.42,2455.58 11474.42,2694.42
  pour cut-out: 12638.43,1419.42 12638.43,1180.58 12877.27,1180.58 12877.27,1419.42
  pour cut-out: 11235.58,1419.42 11235.58,1180.58 11474.42,1180.58 11474.42,1419.42
  pour cut-out: 12329.55,529.55 12329.55,39.55 12829.55,39.55 12829.55,529.55
  pour cut-out: 10950,530 10950,40 11450,40 11450,530
  pour cut-out: 7570,1627.87 7570,1337.87 7750,1337.87 7750,1627.87
  pour cut-out: 7570,3683.94 7570,3393.94 7750,3393.94 7750,3683.94
  pour cut-out: 7570,5740 7570,5450 7750,5450 7750,5740
  pour cut-out: 4410,1456 4410,1246 4880,1246 4880,1456
  pour cut-out: 4410,6510 4410,6300 4880,6300 4880,6510
  pour cut-out: 4600,2323.43 4600,2113.43 4820,2113.43 4820,2323.43
  pour cut-out: 3810,2428.19 3810,2218.19 4030,2218.19 4030,2428.19
  pour cut-out: 4600,4883.43 4600,4673.43 4820,4673.43 4820,4883.43
  pour cut-out: 3810,4983.19 3810,4773.19 4030,4773.19 4030,4983.19
  pour cut-out: 4600,7373.43 4600,7163.43 4820,7163.43 4820,7373.43
  pour cut-out: 3810,7478.19 3810,7268.19 4030,7268.19 4030,7478.19
  pour cut-out: 3810,951.81 3810,741.81 4030,741.81 4030,951.81
  pour cut-out: 3810,6001.81 3810,5791.81 4030,5791.81 4030,6001.81
  pour cut-out: 3810,3506.81 3810,3296.81 4030,3296.81 4030,3506.81
  pour cut-out: 5152.13,1456 5152.13,1246 5562.13,1246 5562.13,1456
  pour cut-out: 2980,1455 2980,1245 3390,1245 3390,1455
  pour cut-out: 5152.13,4025 5152.13,3815 5562.13,3815 5562.13,4025
  pour cut-out: 4410,4025 4410,3815 4880,3815 4880,4025
  pour cut-out: 2980,4010 2980,3790 3390,3790 3390,4010
  pour cut-out: 5152.13,6510 5152.13,6300 5562.13,6300 5562.13,6510
  pour cut-out: 2980,6505 2980,6295 3390,6295 3390,6505
  pour cut-out: 695,4184 695,3890 915,3890 915,4184
  pour cut-out: 690,2237 690,1937.72 910,1937.72 910,2237
  pour cut-out: 1390,2337 1390,1940 1610,1940 1610,2337
  pour cut-out: 1395,4284 1395,3890 1615,3890 1615,4284
  pour cut-out: 1390,6500 1390,6109 1610,6109 1610,6500
  pour cut-out: 5139,3540 5139,3440 5240,3440 5240,3540
  pour cut-out: 1620,3420 1850,3190 1850,2700 1890,2660 3450,2660 3480,2690 3480,3320 3450,3350 3160,3350 3160,2750 3150,2740 2450,2740 2310,2876 2310,3145 2160,3300 2160,3400 1790,3400 1790,3740 2160,3740 2260,3640 2610,3640 2770,3480 2770,3230 3130,3230 3160,3200 3160,3350 2640,3870 2640,4030 2590,4080 1660,4080 1620,4040
  pour cut-out: 1620,870 1850,640 1850,150 1890,110 3450,110 3480,140 3480,770 3450,800 3160,800 3160,200 3150,190 2450,190 2310,326 2310,595 2160,750 2160,850 1790,850 1790,1190 2160,1190 2260,1090 2610,1090 2770,930 2770,680 3130,680 3160,650 3160,800 2640,1320 2640,1480 2590,1530 1660,1530 1620,1490
  pour cut-out: 9512.54,1027.73 9512.54,927.73 9613.54,927.73 9613.54,1027.73
  pour cut-out: 9815,3016.73 9815,2916.73 9916,2916.73 9916,3016.73
  pour cut-out: 9512.54,3084.73 9512.54,2984.73 9613.54,2984.73 9613.54,3084.73
  pour cut-out: 9513.61,5172.74 9513.61,5072.74 9614.61,5072.74 9614.61,5172.74
  pour cut-out: 5919,3750 5919,3650 6020,3650 6020,3750
  pour cut-out: 10723,5220.73 10723,5120.73 10824,5120.73 10824,5220.73
  pour cut-out: 10697,2943.73 10697,2843.73 10798,2843.73 10798,2943.73
  pour cut-out: 6719.82,5747.52 6719.82,5648.19 6821.82,5648.19 6821.82,5747.52
  pour cut-out: 6719.82,1635.4 6719.82,1536.07 6821.82,1536.07 6821.82,1635.4
  pour cut-out: 6719.82,3691.46 6719.82,3592.13 6821.82,3592.13 6821.82,3691.46
  pour cut-out: 9689,4901.13 9678,4890.13 9678,4698.13 9689,4687.13 9781,4687.13 9795,4701.13 9795,4891.13 9785,4901.13
  pour cut-out: 9893,5377.33 9893,5278 9995,5278 9995,5377.33
  pour cut-out: 9689,2845.06 9678,2834.06 9678,2642.06 9689,2631.06 9781,2631.06 9795,2645.06 9795,2835.06 9785,2845.06
  pour cut-out: 9894,3322 9894,3222 9995,3222 9995,3322
  pour cut-out: 9996,1028 9996,953 10070,953 10070,1028
  pour cut-out: 9889.75,1262.75 9896,1269 9991,1269 10000,1260 10000,1171 9995,1166 9901,1166 9889.75,1177.25
  pour cut-out: 9689,789 9678,778 9678,586 9689,575 9781,575 9795,589 9795,779 9785,789
  pour cut-out: 9649,5809 13720,5809 13753,5842 13753,5714 13750,5711 13707,5754 9649,5754
  pour cut-out: 1044,5327 977,5327 977,5260 1044,5260
  pour cut-out: 1288,2542 1221,2542 1221,2475 1288,2475
  pour cut-out: 1109,2542 1042,2542 1042,2475 1109,2475
  pour cut-out: 25.49,7482 25.49,7527 5285,7527 5336,7476 5336,6661 5388,6609 6098,6609 6495,6212 7785,6212 8188,5809 9649,5809 9649,5754 8165,5754 7734.87,6184.13 6442.87,6184.13 6063,6564 5333,6564 5289,6608 5289,7451 5258,7482
  pour cut-out: 4875,5581 4875,5341 4885,5331 4951,5331 4962,5342 4962,5581
  pour cut-out: 4940,5075 4940,4860 4950,4850 5016,4850 5027,4861 5027,5075
  pour cut-out: 4947,3187.5 4947,2943.5 4957,2933.5 5023,2933.5 5034,2944.5 5034,3187.5
  pour cut-out: 4952,2352.5 4946,2346.5 4946,2147.5 4956,2137.5 5022,2137.5 5033,2148.5 5033,2345.5 5026,2352.5
  pour cut-out: 3666,378 3599,378 3599,311 3666,311
  pour cut-out: 3843,395 3776,395 3776,328 3843,328
  pour cut-out: 4052.4,423.6 3985.4,423.6 3985.4,356.6 4052.4,356.6
  pour cut-out: 4075,567 4008,567 4008,500 4075,500
  pour cut-out: 4075,3117 4008,3117 4008,3050 4075,3050
  pour cut-out: 4052.4,2973.6 3985.4,2973.6 3985.4,2906.6 4052.4,2906.6
  pour cut-out: 3843,2945 3776,2945 3776,2878 3843,2878
  pour cut-out: 3666,2928 3599,2928 3599,2861 3666,2861
  pour cut-out: 4075,5617 4008,5617 4008,5550 4075,5550
  pour cut-out: 4052.4,5473.6 3985.4,5473.6 3985.4,5406.6 4052.4,5406.6
  pour cut-out: 3843,5445 3776,5445 3776,5378 3843,5378
  pour cut-out: 3666,5428 3599,5428 3599,5361 3666,5361
  pour cut-out: 1974,438 1907,438 1907,371 1974,371
  pour cut-out: 2060,267 1939,267 1939,168 2060,168
  pour cut-out: 2060,2817 1939,2817 1939,2718 2060,2718
  pour cut-out: 1974,2988 1907,2988 1907,2921 1974,2921
  pour cut-out: 2060,5317 1939,5317 1939,5218 2060,5218
  pour cut-out: 1974,5488 1907,5488 1907,5421 1974,5421
  pour cut-out: 1000,1220 1000,104.97 1079.97,25 1000,25 69,25 25,69 25,1254 105,1334 754,1334 800,1288 932.01,1287.99
  pour cut-out: 5850,5211 5813,5174 5813,4633 5876,4570 6552,4570 6611,4629 6611,5178 6578,5211
  pour cut-out: 6813.78,5211 6776.78,5174 6776.78,4633 6839.78,4570 7515.78,4570 7574.78,4629 7574.78,5178 7541.78,5211
  pour cut-out: 7777.56,5211 7740.56,5174 7740.56,4633 7803.56,4570 8479.56,4570 8538.56,4629 8538.56,5178 8505.56,5211
  pour cut-out: 5850,3154.94 5813,3117.94 5813,2576.94 5876,2513.94 6552,2513.94 6611,2572.94 6611,3121.94 6578,3154.94
  pour cut-out: 6813.78,3150.94 6776.78,3113.94 6776.78,2572.94 6839.78,2509.94 7515.78,2509.94 7574.78,2568.94 7574.78,3117.94 7541.78,3150.94
  pour cut-out: 7777.56,3154.94 7740.56,3117.94 7740.56,2576.94 7803.56,2513.94 8479.56,2513.94 8538.56,2572.94 8538.56,3121.94 8505.56,3154.94
  pour cut-out: 5850,1098.87 5813,1061.87 5813,520.87 5876,457.87 6552,457.87 6611,516.87 6611,1065.87 6578,1098.87
  pour cut-out: 6813.78,1098.87 6776.78,1061.87 6776.78,520.87 6839.78,457.87 7515.78,457.87 7574.78,516.87 7574.78,1065.87 7541.78,1098.87
  pour cut-out: 7777.56,1098.87 7740.56,1061.87 7740.56,520.87 7803.56,457.87 8479.56,457.87 8538.56,516.87 8538.56,1065.87 8505.56,1098.87
  pour cut-out: 8720,5140 8720,4620 8770,4570 9410,4570 9460,4620 9460,5140 9420,5180 9260,5180 9220,5140 9220,4930 9191.13,4901.13 9038.87,4901.13 9010,4930 9010,5140 8970,5180 8760,5180
  pour cut-out: 8720,3083.94 8720,2563.94 8770,2513.94 9410,2513.94 9460,2563.94 9460,3083.94 9420,3123.94 9260,3123.94 9220,3083.94 9220,2873.94 9191.13,2845.06 9038.87,2845.06 9010,2873.93 9010,3083.94 8970,3123.94 8760,3123.94
  pour cut-out: 8720,1027.87 8720,507.87 8770,457.87 9410,457.87 9460,507.88 9460,1027.87 9420,1067.87 9260,1067.87 9220,1027.87 9220,817.87 9191.13,789 9038.87,789 9010,817.87 9010,1027.87 8970,1067.87 8760,1067.87
  pour cut-out: 5631.25,4960.37 5631.25,4721.53 5870.09,4721.53 5870.09,4960.37
  pour cut-out: 7440,4960.37 7440,4721.53 7844.24,4721.53 7844.24,4960.37
  pour cut-out: 9414.06,4960.37 9414.06,4721.53 9652.9,4721.53 9652.9,4960.37
  pour cut-out: 9414.06,2904.31 9414.06,2665.47 9652.9,2665.47 9652.9,2904.31
  pour cut-out: 7440,2904.31 7440,2665.47 7844.24,2665.47 7844.24,2904.31
  pour cut-out: 5631.25,2904.31 5631.25,2665.47 5870.09,2665.47 5870.09,2904.31
  pour cut-out: 9414.06,848.24 9414.06,609.4 9652.9,609.4 9652.9,848.24
  pour cut-out: 7440,848.24 7440,609.4 7844.24,609.4 7844.24,848.24
  pour cut-out: 5631.25,848.24 5631.25,609.4 5870.09,609.4 5870.09,848.24
  pour cut-out: 13480,5770 13760,5770 13760,5950 13480,5950
  pour cut-out: 6167.8,1475 6167.8,1265 6577.8,1265 6577.8,1475
  pour cut-out: 6167.8,1975 6167.8,1765 6577.8,1765 6577.8,1975
  pour cut-out: 6167.8,3535 6167.8,3325 6577.8,3325 6577.8,3535
  pour cut-out: 6167.8,4035 6167.8,3825 6577.8,3825 6577.8,4035
  pour cut-out: 6167.8,6085 6167.8,5875 6577.8,5875 6577.8,6085
  pour cut-out: 6167.8,5585 6167.8,5375 6577.8,5375 6577.8,5585
  text "'.Layer_Name'" at -13,-857 h60
Pwr Layer:
  pour cut-out: 10638,7212 10635,7212 10625.51,7202.51 10625.51,7202 10649.98,7177.53 10660,7187.55 10660,7190
  text "'.Layer_Name'" at -13,-855 h60
Bottom Layer:
  text ".Layer_Name" at -13.55,-858.49 h60

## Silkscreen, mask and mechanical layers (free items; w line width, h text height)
Top Overlay:
  lines w6: 2813,5416 2822,5416 ; 2814,352 2822,352 ; 2814,2905 2823.8,2905 ; 6329,2359 6329,2373 ; 6330,2398 6330,2413 ; 6345,4412 6345,4437 ; 6345,4454 6345,4472 ; 6410,6438.53 6425.93,6454.45 6425.93,6495.5 ; 6491,302 6491,319 ; 6491,343 6491,368 ; 6660,6242.89 6660,6283 ; 6684,6592 6684,6594 ; 6700,6590 6706,6584 6706,6598 6700,6592 6725,6592 ; 6712,6540 6566.93,6540 6566.93,6688 6719,6688 ; 6815,6258 6832.85,6275.85 6832.85,6306.02 ; 6897,6458 6918,6458 6926,6458 6937,6458 6942,6453 6942,6445 ; 7036.41,6935 7036.41,6967 ; 7038,5578 7053,5578 7074,5557 ; 7319.39,6786.73 7328,6778.13 7328,6763 ; 7775.56,1918 7797,1918 ; 7777,3853 7796,3853 ; 7777,5928 7800,5928 ; 7817,1918 7840,1918 ; 7823,5928 7837,5928 ; 7827,3853 7849,3853 ; 7856,7795 7913.13,7795 7917.73,7790.4 ; 7859,7832 7880,7832 7900.2,7852.2 7932.35,7852.2 ; 7887,6596 7861,6596 ; 7902.9,6534.1 7715.9,6534.1 7712.1,6537.9 7712.1,6667.9 7902.9,6667.9 ; 8079,6934 8079,6929 8090.43,6917.57 8090.43,6897.98 ; 8080,6290 8080,5979 8395,5979 8408.7,5979 8408.7,6288 ; 8084,6384 8084,6450 8416,6450 8416,6427 ; 8103,6747 8115,6759 8149,6759 8157.72,6767.72 8157.72,6780.73 ; 8137.98,6920 8157.72,6900.27 ; 8193,6163 8193,6215 ; 8343,6970 8355,6958 8355,6933 ; 8478,6773 8478,6762 8482,6758 8499,6758 ; 8782,6678 8758,6678 ; 9445,6695 9420,6695 ; 10324,7011 10324,7035 ; 10386,7008 10386,7038 ; 10485,7051 10485,7078 ; 10735.34,6709.66 10735.34,6689.46 10735.34,6687.66 10741,6682 ; 10738,6517 10765,6517 10778,6504 10778,6499 ; 6660,6283 6661.04,6283 6670,6274.04 6651.04,6274.04 6656.5,6279.5 6660,6283 ; 7861,6596 7868,6603 7868,6589 7861,6596 ; 8193,6215 8185,6207 8201,6207 8193,6215 ; 8758,6678 8767,6687 8767,6669 8758,6678 ; 9420,6695 9427,6702 9427,6685 9420,6692 9420,6695 ; 6580,6054.98 6742.15,6054.98 6742.15,6505.15 6589.65,6505.15 6580,6495.5 6580,6054.98
  text "GND" at 11290,7602 h60
  text "+15V_IN" at 11772,7304 h60 r90
  text "+3.3V" at 10410,7098 h50
  text "+5V" at 10775,6718 h50 r90
  text "1.65V" at 11031,6456 h25
  text "+12V" at 12186,6283 h60
  text "DC+" at 13528,6019 h80
  text "DC-" at 12490.55,5991.55 h80
  text "PHASE-C" at 32,5976 h80
  text "Q9" at 7158,5169 h30
  text "Q12" at 9059,5165 h30
  text "Q11" at 8109,5162 h30
  text "Q10" at 6229,5161 h30
  text "PHASE-B" at 37,3760 h80
  text "Q7" at 8142,3115 h30
  text "Q6" at 6207,3111 h30
  text "Q5" at 7171,3110 h30
  text "Q8" at 9092,3108 h30
  text "PHASE-A" at 32,1813 h80
  text "Q3" at 8112,1059 h30
  text "Q4" at 9120,1056 h30
  text "Q2" at 6217,1055 h30
  text "Q1" at 7174,1053 h30
  text "NEUTRAL" at 32,621 h80
  text "DC-" at 11099,517 h80
  text "DC+" at 12478.55,516.55 h80
  text "'.PRJ_Number'.PCB_Rev" at 7557,103 h200
  text ".Layer_Name" at -13.55,-858.49 h60
Bottom Overlay:
  text ".Layer_Name" at -13.55,-858.49 h60
Top Paste:
  text ".Layer_Name" at -13.55,-858.49 h60
Bottom Paste:
  text ".Layer_Name" at -13.55,-858.49 h60
Top Solder:
  text ".Layer_Name" at -13.55,-858.49 h60
  text ".Layer_Name" at -13.55,-858.49 h60
Bottom Solder:
  text ".Layer_Name" at -13.55,-858.49 h60
Drill Guide:
  text ".Layer_Name" at -13.55,-858.49 h60
M1 Board Outline:
  the board outline again, w10
M2 Board Dimensions:
  rectangle: -590.55,-275 -465.55,-150
  rectangle: -465.55,-400 -90.55,-275
  lines w7: -590.55,-275 409.45,-275 ; -465.55,-400 -465.55,-150 ; -340.55,-400 -340.55,-150 ; -90.55,-400 -90.55,-150 ; 159.45,-400 159.45,-150 ; -590.55,-400 409.45,-400 409.45,-150 -590.55,-150 -590.55,-400
M3 3D STEP Top:
  text ".Layer_Name" at -13.55,-858.49 h60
